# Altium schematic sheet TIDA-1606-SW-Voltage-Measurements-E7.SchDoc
size 431 x 279 mm; Date: Not shown in title block; ApprovedBy: Not shown in title block; CheckedBy: Not shown in title block; Author: Not shown in title block; CompanyName: Not shown in title block; Engineer: Not shown in title block; Organization: Not shown in title block; Address1: Not shown in title block; Address2: Not shown in title block; Address3: Not shown in title block; Address4: Not shown in title block; DocumentNumber: 6; Revision: Use project parameter SCH_Rev; SheetNumber: 6; SheetTotal: 16; PageSetup: Record=PageOptions¦CenterHorizontal=True¦CenterVertical=True¦PrintScale=1.00¦XCorrection=1.00¦YCorrection=1.00¦PrintKind=0¦BorderSize=5000000¦LeftOffset=0¦BottomOffset=0¦Orientation=2¦PaperLength=1000¦PaperWidth=1000¦Scale=100¦PaperSource=15¦PrintQuality=600¦MediaType=1¦DitherType=10¦PaperKind=Letter¦PrintScaleMode=1
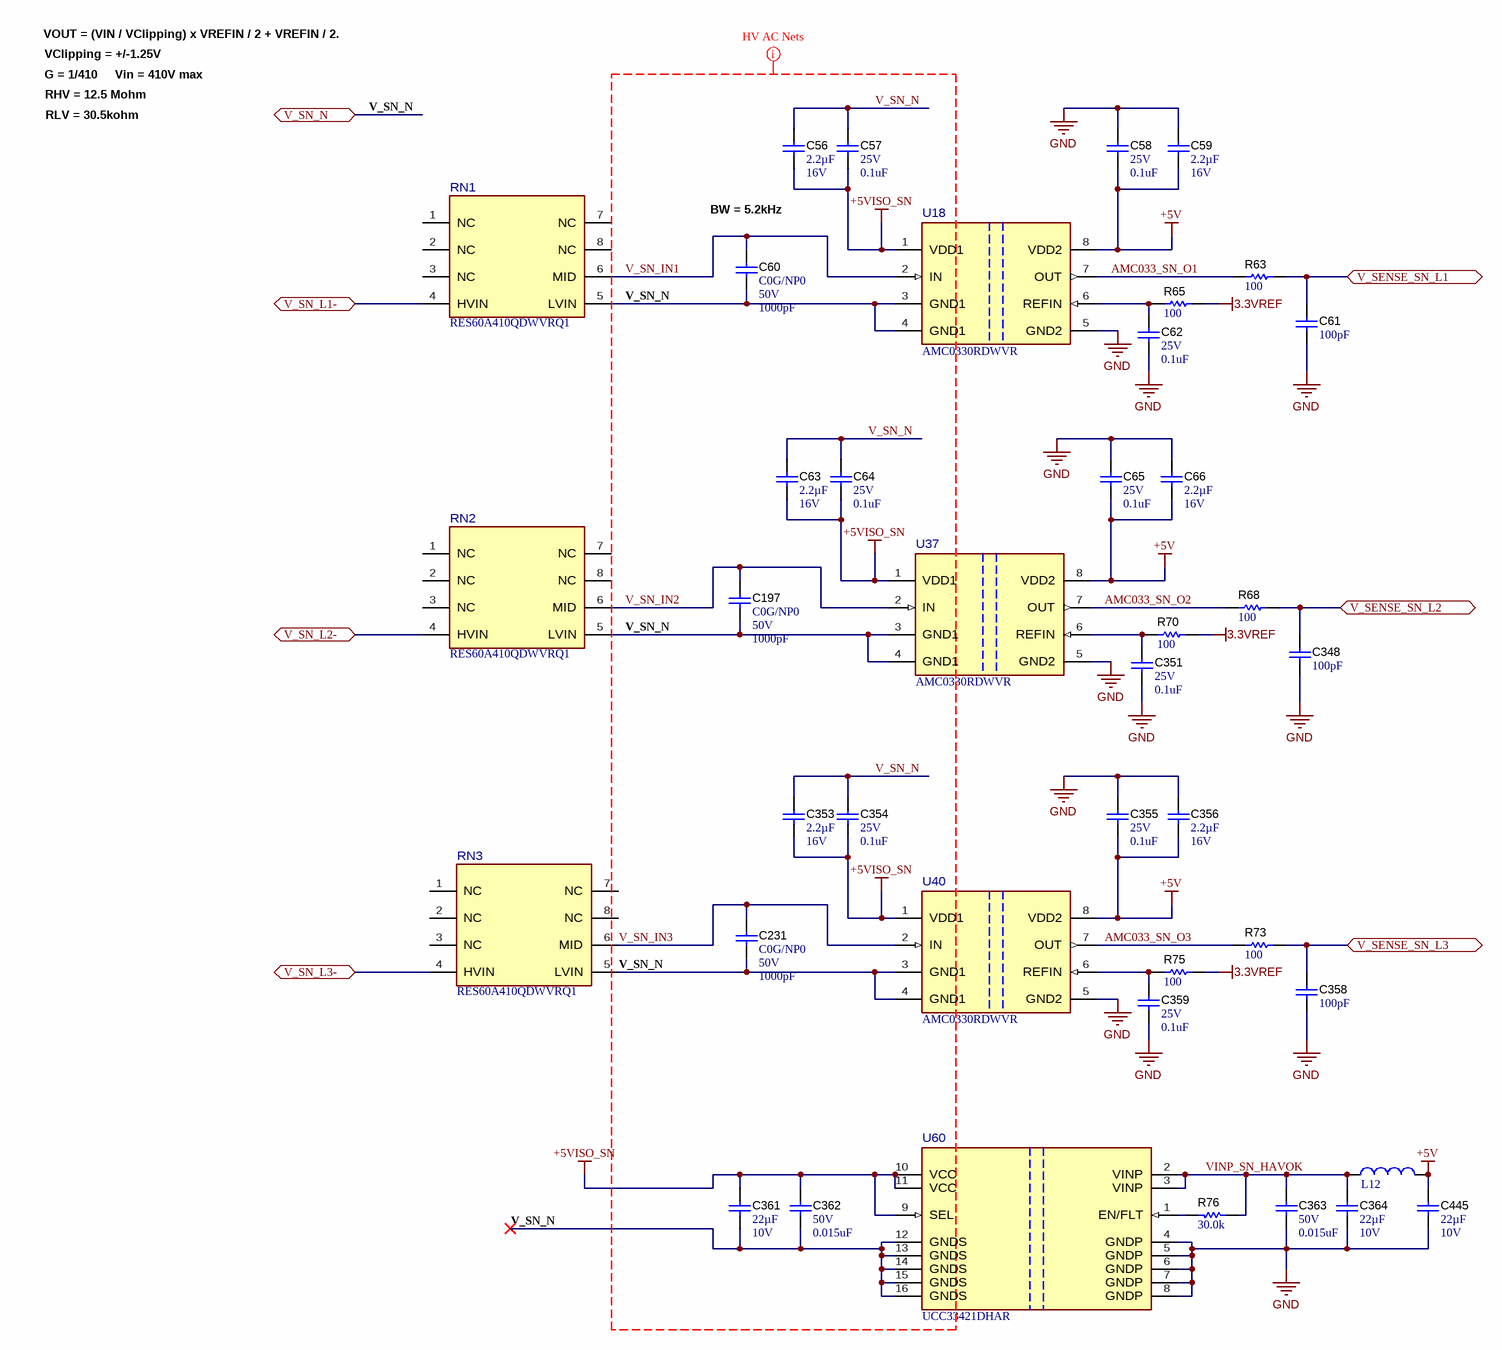
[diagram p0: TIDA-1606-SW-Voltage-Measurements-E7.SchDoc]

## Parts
C56  Cap_F: 2.2µF  VDC_V: 16V  [0603]  (hidden comment: EMK107BB7225KA-T)
C57  VDC_V: 25V  ValueDisplayed: 0.1uF  [0402L]  (hidden comment: GRM155R71E104KE14D)
C58  VDC_V: 25V  ValueDisplayed: 0.1uF  [0402L]  (hidden comment: GRM155R71E104KE14D)
C59  Cap_F: 2.2µF  VDC_V: 16V  [0603]  (hidden comment: EMK107BB7225KA-T)
C60  TempCo: C0G/NP0  VDC_V: 50V  ValueDisplayed: 1000pF  [0402L]  (hidden comment: CGA2B2C0G1H102J050BA)
C61  ValueDisplayed: 100pF  [0402L]  (hidden comment: GRM1555C1H101JA01D)
C62  VDC_V: 25V  ValueDisplayed: 0.1uF  [0402L]  (hidden comment: GRM155R71E104KE14D)
C63  Cap_F: 2.2µF  VDC_V: 16V  [0603]  (hidden comment: EMK107BB7225KA-T)
C64  VDC_V: 25V  ValueDisplayed: 0.1uF  [0402L]  (hidden comment: GRM155R71E104KE14D)
C65  VDC_V: 25V  ValueDisplayed: 0.1uF  [0402L]  (hidden comment: GRM155R71E104KE14D)
C66  Cap_F: 2.2µF  VDC_V: 16V  [0603]  (hidden comment: EMK107BB7225KA-T)
C197  TempCo: C0G/NP0  VDC_V: 50V  ValueDisplayed: 1000pF  [0402L]  (hidden comment: CGA2B2C0G1H102J050BA)
C231  TempCo: C0G/NP0  VDC_V: 50V  ValueDisplayed: 1000pF  [0402L]  (hidden comment: CGA2B2C0G1H102J050BA)
C348  ValueDisplayed: 100pF  [0402L]  (hidden comment: GRM1555C1H101JA01D)
C351  VDC_V: 25V  ValueDisplayed: 0.1uF  [0402L]  (hidden comment: GRM155R71E104KE14D)
C353  Cap_F: 2.2µF  VDC_V: 16V  [0603]  (hidden comment: EMK107BB7225KA-T)
C354  VDC_V: 25V  ValueDisplayed: 0.1uF  [0402L]  (hidden comment: GRM155R71E104KE14D)
C355  VDC_V: 25V  ValueDisplayed: 0.1uF  [0402L]  (hidden comment: GRM155R71E104KE14D)
C356  Cap_F: 2.2µF  VDC_V: 16V  [0603]  (hidden comment: EMK107BB7225KA-T)
C358  ValueDisplayed: 100pF  [0402L]  (hidden comment: GRM1555C1H101JA01D)
C359  VDC_V: 25V  ValueDisplayed: 0.1uF  [0402L]  (hidden comment: GRM155R71E104KE14D)
C361  Cap_F: 22µF  VDC_V: 10V  [0805_HV]  (hidden comment: GRM21BZ71A226ME15L)
C362  VDC_V: 50V  ValueDisplayed: 0.015uF  [0402L]  (hidden comment: CGA2B3X7R1H153K050BB)
C363  VDC_V: 50V  ValueDisplayed: 0.015uF  [0402L]  (hidden comment: CGA2B3X7R1H153K050BB)
C364  Cap_F: 22µF  VDC_V: 10V  [0805_HV]  (hidden comment: GRM21BZ71A226ME15L)
C445  Cap_F: 22µF  VDC_V: 10V  [0805_HV]  (hidden comment: GRM21BZ71A226ME15L)
L12  74479763222  [WE-PMI_0603_L1.6W0.8H0.8]  (value not drawn)
R63  ValueDisplayed: 100  [0402L]  (hidden comment: ERJ-2RKF1000X)
R65  ValueDisplayed: 100  [0402L]  (hidden comment: ERJ-2RKF1000X)
R68  ValueDisplayed: 100  [0402L]  (hidden comment: ERJ-2RKF1000X)
R70  ValueDisplayed: 100  [0402L]  (hidden comment: ERJ-2RKF1000X)
R73  ValueDisplayed: 100  [0402L]  (hidden comment: ERJ-2RKF1000X)
R75  ValueDisplayed: 100  [0402L]  (hidden comment: ERJ-2RKF1000X)
R76  ValueDisplayed: 30.0k  [0402L]  (hidden comment: CRCW040230K0FKED)
RN1  RES60A410QDWVRQ1  [DWV0008A-MFG]
RN2  RES60A410QDWVRQ1  [DWV0008A-MFG]
RN3  RES60A410QDWVRQ1  [DWV0008A-MFG]
U18  AMC0330RDWVR  [DWV0008A-MFG]
U37  AMC0330RDWVR  [DWV0008A-MFG]
U40  AMC0330RDWVR  [DWV0008A-MFG]
U60  UCC33421DHAR  [DHA0016A-MFG]

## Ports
V_SENSE_SN_L1 (bidir), V_SENSE_SN_L2 (bidir), V_SENSE_SN_L3 (bidir), V_SN_L1- (bidir), V_SN_L2- (bidir), V_SN_L3- (bidir), V_SN_N (bidir)

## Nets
3.3VREF: R65.2 R70.2 R75.2
+5V: C58.2 C59.1 C65.2 C66.1 C355.2 C356.1 C445.1 L12.2 U18.8(VDD2) U37.8(VDD2) U40.8(VDD2)
+5VISO_SN: C56.1 C57.2 C63.1 C64.2 C353.1 C354.2 C361.1 C362.1 U18.1(VDD1) U37.1(VDD1) U40.1(VDD1) U60.9(SEL) U60.10(VCC) U60.11(VCC)
GND: C58.1 C59.2 C61.2 C62.2 C65.1 C66.2 C348.2 C351.2 C355.1 C356.2 C358.2 C359.2 C363.2 C364.2 C445.2 U18.5(GND2) U37.5(GND2) U40.5(GND2) U60.4(GNDP) U60.5(GNDP) U60.6(GNDP) U60.7(GNDP) U60.8(GNDP)
AMC033_SN_O1: R63.1 U18.7(OUT)
AMC033_SN_O2: R68.1 U37.7(OUT)
AMC033_SN_O3: R73.1 U40.7(OUT)
V_SENSE_SN_L1: C61.1 R63.2 ; port V_SENSE_SN_L1
V_SENSE_SN_L2: C348.1 R68.2 ; port V_SENSE_SN_L2
V_SENSE_SN_L3: C358.1 R73.2 ; port V_SENSE_SN_L3
V_SN_IN1: C60.1 RN1.6(MID) U18.2(IN)
V_SN_IN2: C197.1 RN2.6(MID) U37.2(IN)
V_SN_IN3: C231.1 RN3.6(MID) U40.2(IN)
V_SN_L1-: RN1.4(HVIN) ; port V_SN_L1-
V_SN_L2-: RN2.4(HVIN) ; port V_SN_L2-
V_SN_L3-: RN3.4(HVIN) ; port V_SN_L3-
V_SN_N: C56.2 C57.1 C60.2 C63.2 C64.1 C197.2 C231.2 C353.2 C354.1 C361.2 C362.2 RN1.5(LVIN) RN2.5(LVIN) RN3.5(LVIN) U18.3(GND1) U18.4(GND1) U37.3(GND1) U37.4(GND1) U40.3(GND1) U40.4(GND1) U60.12(GNDS) U60.13(GNDS) U60.14(GNDS) U60.15(GNDS) U60.16(GNDS) ; port V_SN_N
VINP_SN_HAVOK: C363.1 C364.1 L12.1 R76.1 U60.2(VINP) U60.3(VINP)
NetC62_1: C62.1 R65.1 U18.6(REFIN)
NetC351_1: C351.1 R70.1 U37.6(REFIN)
NetC359_1: C359.1 R75.1 U40.6(REFIN)
NetR76_2: R76.2 U60.1(EN/FLT)

Not connected (* = marked no-connect by the designer): RN1 1(NC) 2(NC) 3(NC) 7(NC) 8(NC); RN2 1(NC) 2(NC) 3(NC) 7(NC) 8(NC); RN3 1(NC) 2(NC) 3(NC) 7(NC) 8(NC)

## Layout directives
net class HV_AC1; net class HV_VSEN_SN: +5VISO_SN, V_SN_IN1, V_SN_IN2, V_SN_IN3, V_SN_N

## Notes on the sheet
- G = 1/410
- VClipping = +/-1.25V
- Vin = 410V max
- VOUT = (VIN / VClipping) x VREFIN / 2 + VREFIN / 2.
- RLV = 30.5kohm
- RHV = 12.5 Mohm
- BW = 5.2kHz

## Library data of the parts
C56 C59 C63 C66 C353 C356 = CMP-0007121-4: CAP, CERM, 2.2 uF, 16 V, +/- 10%, X7R, 0603; Manufacturer: Taiyo Yuden; TaMin_C: -55°C; Polarized: N; SizeAreaWB_mm2: 4.68; Value1: Unknown; U/M: EA; Value: 2.2uF; TaMax_C: 125°C; SizeZ_mm: 1; SizeX_mm: 1.6; SizeY_mm: 0.8; SizeArea_mm2: 1.28; AEC Category: Q200
C57 C58 C62 C64 C65 C351 C354 C355 C359 = CMP-0006659-2: CAP, CERM, 0.1 uF, 25 V, +/- 10%, X7R, 0402; Manufacturer: MuRata; TaMin_C: -55°C; Polarized: N; SizeAreaWB_mm2: 3; Value1: Unknown; U/M: EA; Value: 0.1uF; TaMax_C: 125°C; SizeZ_mm: 0.6; SizeX_mm: 1; SizeY_mm: 0.5; Cap_Case: 0402; Cap_F: 100nF; AEC Category: Q200
C60 C197 C231 = CMP-0006309-2: CAP, CERM, 1000 pF, 50 V, +/- 5%, C0G/NP0, AEC-Q200 Grade 1, 0402; Manufacturer: TDK; TaMin_C: -55°C; Polarized: N; SizeAreaWB_mm2: 3; Value1: Unknown; U/M: EA; Value: 1000pF; TaMax_C: 125°C; SizeZ_mm: 0.6; SizeX_mm: 1; SizeY_mm: 0.5; Cap_Case: 0402; AEC Qualified: Y; Cap_F: 1nF; AEC Category: Q200
C61 C348 C358 = CMP-0006410-2: CAP, CERM, 100 pF, 50 V, +/- 5%, C0G/NP0, 0402; Manufacturer: MuRata; TaMin_C: -55°C; Polarized: N; SizeAreaWB_mm2: 3; Value1: Unknown; U/M: EA; Value: 100pF; TaMax_C: 125°C; SizeZ_mm: 0.6; SizeX_mm: 1; SizeY_mm: 0.5; Cap_Case: 0402; Value2: 50V; AEC Category: Q200
C361 C364 C445 = CMP-0008377-2: CAP, CERM, 22 uF, 10 V, +/- 20%, X7R, 0805; Manufacturer: MuRata; SizeY_mm: 1.25; Cap_Case: 0805; SizeArea_mm2: 2.5; AEC Qualified: N; AEC Category: Q200; ValueDisplayed: 22uF; TaMin_C: -55°C; SizeAreaWB_mm2: 6.75; Value1: Unknown; U/M: EA; Value: 22uF; TaMax_C: 125°C; SizeZ_mm: 1.45; SizeX_mm: 2
C362 C363 = CMP-0006327-2: CAP, CERM, 0.015 uF, 50 V, +/- 10%, X7R, AEC-Q200 Grade 1, 0402; Manufacturer: TDK; TaMin_C: -55°C; ESR_ohm: 0.2162; Polarized: N; SizeAreaWB_mm2: 3; Value1: 0.2162 ohm; U/M: EA; TaMax_C: 125°C; SizeZ_mm: 0.6; SizeX_mm: 1; SizeY_mm: 0.5; Cap_Case: 0402; AEC Qualified: Y; Cap_F: 15nF; IRMS_A: 379.389mA; AEC Category: Q200
L12 = CMP-0100992-1: WE-PMI SMT Power Multilayer Inductor, size 0603, 2.2uH, 0.8A, 375mOhm; Manufacturer: Wurth Elektronik; Case/Size Code: 0603; Inductance Tolerance: 20%; Q Factor: 15; Saturation Current: 0.28A; Self Resonant Frequency: 80MHz; Type: Low RDC
R63 R65 R68 R70 R73 R75 = CMP-0026656-1: RES, 100, 1%, 0.1 W, 0402; Manufacturer: Panasonic; Power_W: 100mW; TempCo: 100 ppm/C; Value_Code: 100R; U/M: EA; Value: 100; EIA_Code: E96; SizeX_mm: 1; SizeY_mm: 0.5; SizeZ_mm: 0.6; Value2: 0.1W; VDC_V: 50V; AEC Category: Q200
R76 = CMP-0078244-2: RES, 30.0 k, 1%, 0.063 W, AEC-Q200 Grade 0, 0402; Manufacturer: Vishay-Dale; Power_W: 63mW; Green_Lifecycle: Active; TempCo: 100 ppm/C; Value_Code: 30k0; Green_REACh: Passed; Value: 30.0k; Res_ohm: 30k; SizeX_mm: 1; SizeY_mm: 0.5; SizeZ_mm: 0.6; Value2: 0.063W; AEC Qualified: Y; VDC_V: 50V; AEC Grade: 0; AEC Category: Q200
RN1-RN3 = CMP-0122946-1: Automotive, 1700-V, Precision Resistive Divider; Manufacturer: Texas Instruments; SizeZ_mm: 2.8mm; AEC Qualified: Yes; AEC Grade: Grade 1; Number Of Resistors: 2; Standoff Height: 0.36mm; TaMax_C: +125°C; TaMin_C: -40°C; TempCo: 1ppm/°C; TJmax_C: +150°C; Tolerance_%: 0.05%; VDC_V: 1700V
U18 U37 U40 = CMP-0122725-1: Automotive, Precision, ±1V Input Isolated Amplifiers With Single-Ended, Ratiometric Output; Manufacturer: Texas Instruments; SizeZ_mm: 2.8mm; AEC Qualified: Yes; AEC Grade: Grade 1; Bandwidth: 110kHz; Input Bias Current: 0.0035uA; Input Offset Voltage: 0.4mV; Max Supply Voltage: 5.5V; Min Supply Voltage: 3V; Number Of Channels: 1; Output Current Per Channel: 14mA; Response Time: 500us; Standoff Height: 0.36mm; TaMax_C: +125°C; TaMin_C: -40°C; TJmax_C: +150°C
U60 = CMP-0123146-1: Ultra-Small, 1.5W, 5.0V, 5kVRMS Isolation, Industrial DC/DC Module; Manufacturer: Texas Instruments; SizeZ_mm: 2.6mm; AEC Qualified: No; Max Supply Voltage: 5.5V; Min Supply Voltage: 4.5V; Nominal Supply Current: 7-545mA; Number Of Outputs: 1; Output Type: AdjustableProgrammable; Output Voltage: 5/5.5V; Standoff Height: 0.1mm; Switching Frequency: 76MHz; Switching Topology: Boost; TaMax_C: +125°C; TaMin_C: -40°C; TJmax_C: +150°C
